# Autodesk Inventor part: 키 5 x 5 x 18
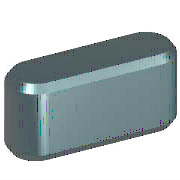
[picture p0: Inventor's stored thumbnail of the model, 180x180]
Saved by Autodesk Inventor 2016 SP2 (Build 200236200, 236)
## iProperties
Created: 2012-02
Part Number: 키 5 x 5 x 18
Material: 강철, 연강
Description: 키 및 해당 키홈
Document SubType Name: Modeling
Standard: KS B 1311
Designer: P15F
Standards Organization: KS
Language: ko-KR
Size Designation: 5 x 5 x 18
Categories: <MemberInstance><Categories><Category DisplayName="샤프트 부품" InternalName="7f7aeb1f-a693-4053-b835-cee3144e0d98" Mnemonic="SHFT"><Category DisplayName="키" Interna
Density: 1 g/cm^3
Appearance: 노란색
IsCustomPart: 1
Author: P15F
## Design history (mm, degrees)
workplane "Work Plane1"
workplane "Work Plane2"
sketch "스케치1"
  geometry: L1 (2.5, 2.5)-(15.5, 2.5); L2 (15.5, -2.5)-(2.5, -2.5); L3 (0, 9.4)-(0, -7.4) reference; L4 (-5, 0)-(30, 0) reference; L5 (18, 0)-(18, 7); A1 r 2.5 centre (2.5, 0) between (2.5, 2.5) and (2.5, -2.5); A2 r 2.5 centre (15.5, 0) between (15.5, -2.5) and (15.5, 2.5)
  constraints: 6 end point, 5 point on circle, 4 tangent, 3 point on line, 2 centre point, 1 horizontal, 1 parallel, 1 perpendicular
  dimensions: "d0" = 2.5 radius of A1 (= 0.5 x PB); "d13" = 2.5 radius of A2 (= 0.5 x PB); "d14" = 18 distance between parallel lines of L5 L3 (= NLG)
extrude "본체1" new body sketch "스케치1" taper "d3" = 0 deg; stored distance "d4" = 10
workplane "Work Plane3"
body "Solid1"
chamfer "모따기1" distance "d8" = 0.4 (= PHH); stored, may be unused: second distance "d9" = 0.4 (= PHH), angle "d15" = 45 deg
other parameters: "d1" = -3 (= -PNT), "d2" = 2 (= PH - PNT), "NLG" = 18 [user parameter; used in 3 equation terms], "PB" = 5 [user parameter; used in 2 equation terms], "PNT" = 3 [user parameter; used in 2 equation terms], "PH" = 5 [user parameter; used in 1 equation term], "PHH" = 0.4 [user parameter; used in 2 equation terms], "d10" = 0, "d16" = 0, "d17" = 0, "d18" = 0, "WDMIN" = 12 [user parameter], "PLB2" = 18 (= NLG) [user parameter], "WDMAX" = 17 [user parameter], "PLB1" = 18 (= NLG) [user parameter], "RR" = 0.16 [user parameter], "PUEB" = 2.3 [user parameter]
